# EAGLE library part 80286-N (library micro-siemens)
MICROPROCESSOR/PERIPHERAL DEVICE
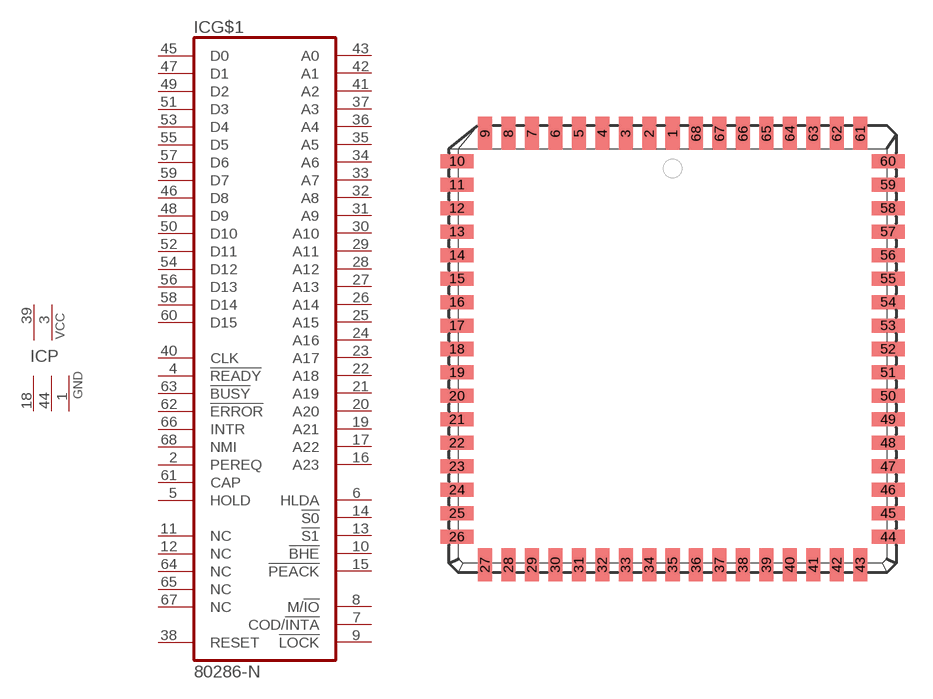
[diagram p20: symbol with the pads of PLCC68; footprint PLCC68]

Designator prefix IC; gates G$1=80286 P=2VCC3GND

## 80286-N (OC_FARNELL: unknown; OC_NEWARK: unknown)  [PLCC68]
1  P:GND  pwr
2  G$1:PEREQ  in
3  P:VCC  pwr
4  G$1:!READY  in
5  G$1:HOLD  in
6  G$1:HLDA  out
7  G$1:COD/!INTA  out
8  G$1:M/!IO  out
9  G$1:!LOCK  out
10  G$1:!BHE  out
11  G$1:NC  nc
12  G$1:NC  nc
13  G$1:!S1  out
14  G$1:!S0  out
15  G$1:!PEACK  out
16  G$1:A23  out
17  G$1:A22  out
18  P:GND  pwr
19  G$1:A21  out
20  G$1:A20  out
21  G$1:A19  out
22  G$1:A18  out
23  G$1:A17  out
24  G$1:A16  out
25  G$1:A15  out
26  G$1:A14  out
27  G$1:A13  out
28  G$1:A12  out
29  G$1:A11  out
30  G$1:A10  out
31  G$1:A9  out
32  G$1:A8  out
33  G$1:A7  out
34  G$1:A6  out
35  G$1:A5  out
36  G$1:A4  out
37  G$1:A3  out
38  G$1:RESET  in
39  P:VCC  pwr
40  G$1:CLK  in
41  G$1:A2  out
42  G$1:A1  out
43  G$1:A0  out
44  P:GND  pwr
45  G$1:D0
46  G$1:D8
47  G$1:D1
48  G$1:D9
49  G$1:D2
50  G$1:D10
51  G$1:D3
52  G$1:D11
53  G$1:D4
54  G$1:D12
55  G$1:D5
56  G$1:D13
57  G$1:D6
58  G$1:D14
59  G$1:D7
60  G$1:D15
61  G$1:CAP  in
62  G$1:!ERROR  in
63  G$1:!BUSY  in
64  G$1:NC  nc
65  G$1:NC  nc
66  G$1:INTR  in
67  G$1:NC  nc
68  G$1:NMI  in

## Footprint PLCC68 (pad centres in mm)
PLASTIC LEADED CHIP CARRIER square
smd 0.76 x 1.8: 1 0,11.67; 2 -1.27,11.67; 3 -2.54,11.67; 4 -3.81,11.67; 5 -5.08,11.67; 6 -6.35,11.67; 7 -7.62,11.67; 8 -8.89,11.67; 9 -10.16,11.67; 27 -10.16,-11.67; 28 -8.89,-11.67; 29 -7.62,-11.67; 30 -6.35,-11.67; 31 -5.08,-11.67; 32 -3.81,-11.67; 33 -2.54,-11.67; 34 -1.27,-11.67; 35 0,-11.67; 36 1.27,-11.67; 37 2.54,-11.67; 38 3.81,-11.67; 39 5.08,-11.67; 40 6.35,-11.67; 41 7.62,-11.67; 42 8.89,-11.67; 43 10.16,-11.67; 61 10.16,11.67; 62 8.89,11.67; 63 7.62,11.67; 64 6.35,11.67; 65 5.08,11.67; 66 3.81,11.67; 67 2.54,11.67; 68 1.27,11.67
smd 1.8 x 0.76: 10 -11.67,10.16; 11 -11.67,8.89; 12 -11.67,7.62; 13 -11.67,6.35; 14 -11.67,5.08; 15 -11.67,3.81; 16 -11.67,2.54; 17 -11.67,1.27; 18 -11.67,0; 19 -11.67,-1.27; 20 -11.67,-2.54; 21 -11.67,-3.81; 22 -11.67,-5.08; 23 -11.67,-6.35; 24 -11.67,-7.62; 25 -11.67,-8.89; 26 -11.67,-10.16; 44 11.67,-10.16; 45 11.67,-8.89; 46 11.67,-7.62; 47 11.67,-6.35; 48 11.67,-5.08; 49 11.67,-3.81; 50 11.67,-2.54; 51 11.67,-1.27; 52 11.67,0; 53 11.67,1.27; 54 11.67,2.54; 55 11.67,3.81; 56 11.67,5.08; 57 11.67,6.35; 58 11.67,7.62; 59 11.67,8.89; 60 11.67,10.16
